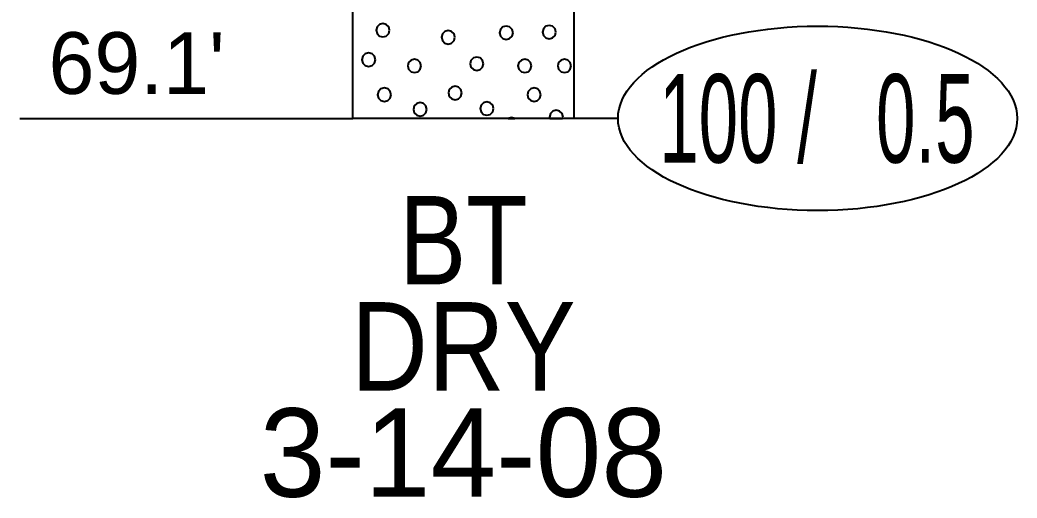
# Model space of a CAD drawing. Extents: x -582 to 653, y -817 to -3.
# Drawn here: x -484.18 to -472.9, y -253.7 to -248.3 of the extents above; entities that cross this region are included whole.
import ezdxf
from ezdxf.enums import TextEntityAlignment as Align

# ---------------------------------------------------------------- set-up
doc = ezdxf.new("R2010")
doc.units = 0
doc.header["$LTSCALE"] = 0.4
doc.layers.add('27', color=7, linetype='Continuous', lineweight=40)

msp = doc.modelspace()

# ---------------------------------------------------------------- linework, layer by layer
at = {"layer": '27'}
for p, q in [((-484.1783, -249.408), (-480.4109, -249.408)), ((-477.4109, -249.408), (-477.9109, -249.408))]:
    msp.add_line(p, q, dxfattribs=at)
for points in [[(-480.4109, -241.308), (-477.9109, -241.308), (-477.9109, -249.408), (-480.4109, -249.408)], [(-479.9951, -248.4114), (-480.0053, -248.3733), (-480.0332, -248.3454), (-480.0713, -248.3352), (-480.1094, -248.3454), (-480.1373, -248.3733), (-480.1475, -248.4114), (-480.1373, -248.4495), (-480.1094, -248.4774), (-480.0713, -248.4876), (-480.0332, -248.4774), (-480.0053, -248.4495)], [(-479.2565, -248.4915), (-479.2667, -248.4534), (-479.2946, -248.4255), (-479.3327, -248.4153), (-479.3708, -248.4255), (-479.3987, -248.4534), (-479.4089, -248.4915), (-479.3987, -248.5296), (-479.3708, -248.5575), (-479.3327, -248.5677), (-479.2946, -248.5575), (-479.2667, -248.5296)], [(-478.5993, -248.4407), (-478.6095, -248.4026), (-478.6374, -248.3747), (-478.6755, -248.3645), (-478.7136, -248.3747), (-478.7414, -248.4026), (-478.7517, -248.4407), (-478.7414, -248.4788), (-478.7136, -248.5067), (-478.6755, -248.5169), (-478.6374, -248.5067), (-478.6095, -248.4788)], [(-478.1136, -248.433), (-478.1238, -248.3949), (-478.1517, -248.367), (-478.1898, -248.3568), (-478.2279, -248.367), (-478.2558, -248.3949), (-478.266, -248.433), (-478.2558, -248.4711), (-478.2279, -248.499), (-478.1898, -248.5092), (-478.1517, -248.499), (-478.1238, -248.4711)], [(-480.1566, -248.7445), (-480.1668, -248.7064), (-480.1947, -248.6785), (-480.2328, -248.6683), (-480.2709, -248.6785), (-480.2988, -248.7064), (-480.309, -248.7445), (-480.2988, -248.7826), (-480.2709, -248.8105), (-480.2328, -248.8207), (-480.1947, -248.8105), (-480.1668, -248.7826)], [(-479.6379, -248.8144), (-479.6481, -248.7763), (-479.676, -248.7484), (-479.7141, -248.7382), (-479.7522, -248.7484), (-479.7801, -248.7763), (-479.7903, -248.8144), (-479.7801, -248.8525), (-479.7522, -248.8804), (-479.7141, -248.8906), (-479.676, -248.8804), (-479.6481, -248.8525)], [(-478.9336, -248.7915), (-478.9438, -248.7534), (-478.9717, -248.7255), (-479.0098, -248.7153), (-479.0479, -248.7255), (-479.0758, -248.7534), (-479.086, -248.7915), (-479.0758, -248.8296), (-479.0479, -248.8575), (-479.0098, -248.8677), (-478.9717, -248.8575), (-478.9438, -248.8296)], [(-478.3908, -248.8144), (-478.401, -248.7763), (-478.4289, -248.7484), (-478.467, -248.7382), (-478.5051, -248.7484), (-478.533, -248.7763), (-478.5432, -248.8144), (-478.533, -248.8525), (-478.5051, -248.8804), (-478.467, -248.8906), (-478.4289, -248.8804), (-478.401, -248.8525)], [(-477.9407, -248.8144), (-477.9509, -248.7763), (-477.9788, -248.7484), (-478.0169, -248.7382), (-478.055, -248.7484), (-478.0829, -248.7763), (-478.0931, -248.8144), (-478.0829, -248.8525), (-478.055, -248.8804), (-478.0169, -248.8906), (-477.9788, -248.8804), (-477.9509, -248.8525)], [(-479.979, -249.1407), (-479.9892, -249.1026), (-480.0171, -249.0747), (-480.0552, -249.0645), (-480.0933, -249.0747), (-480.1212, -249.1026), (-480.1314, -249.1407), (-480.1212, -249.1788), (-480.0933, -249.2067), (-480.0552, -249.2169), (-480.0171, -249.2067), (-479.9892, -249.1788)], [(-479.1781, -249.1211), (-479.1883, -249.083), (-479.2162, -249.0551), (-479.2543, -249.0449), (-479.2924, -249.0551), (-479.3202, -249.083), (-479.3305, -249.1211), (-479.3202, -249.1592), (-479.2924, -249.1871), (-479.2543, -249.1973), (-479.2162, -249.1871), (-479.1883, -249.1592)], [(-478.2844, -249.1407), (-478.2946, -249.1026), (-478.3225, -249.0748), (-478.3606, -249.0645), (-478.3987, -249.0748), (-478.4266, -249.1026), (-478.4368, -249.1407), (-478.4266, -249.1788), (-478.3987, -249.2067), (-478.3606, -249.2169), (-478.3225, -249.2067), (-478.2946, -249.1788)], [(-478.819, -249.297), (-478.8292, -249.2589), (-478.8571, -249.231), (-478.8952, -249.2208), (-478.9333, -249.231), (-478.9612, -249.2589), (-478.9714, -249.297), (-478.9612, -249.3351), (-478.9333, -249.363), (-478.8952, -249.3732), (-478.8571, -249.363), (-478.8292, -249.3351)], [(-479.5741, -249.306), (-479.5843, -249.2679), (-479.6122, -249.24), (-479.6503, -249.2298), (-479.6884, -249.24), (-479.7163, -249.2679), (-479.7265, -249.306), (-479.7163, -249.3441), (-479.6884, -249.3719), (-479.6503, -249.3822), (-479.6122, -249.3719), (-479.5843, -249.3441)], [(-478.0335, -249.3928), (-478.0438, -249.3547), (-478.0716, -249.3269), (-478.1097, -249.3166), (-478.1478, -249.3269), (-478.1757, -249.3547), (-478.1859, -249.3928), (-478.1819, -249.408), (-478.0376, -249.408)], [(-478.617, -249.398), (-478.6545, -249.408), (-478.5795, -249.408)]]:
    msp.add_lwpolyline(points, close=True, dxfattribs=at)
msp.add_ellipse((-475.1536, -249.408), major_axis=(2.2574, 0), ratio=0.461538, dxfattribs=at)

# ---------------------------------------------------------------- texts
msp.add_text("69.1'", height=0.6976, dxfattribs=at).set_placement((-483.8543, -249.1316))
for s, width, p in [('100 /   0.5', 0.6, (-475.1609, -249.908)), ('BT', 0.85, (-479.1609, -251.2849)), ('DRY', 0.9, (-479.1609, -252.4849))]:
    msp.add_text(s, height=1, dxfattribs=dict(at, width=width)).set_placement(p, align=Align.CENTER)
msp.add_text('3-14-08', height=1, dxfattribs=at).set_placement((-479.161, -253.6849), align=Align.CENTER)

doc.saveas('drawing.dxf')
